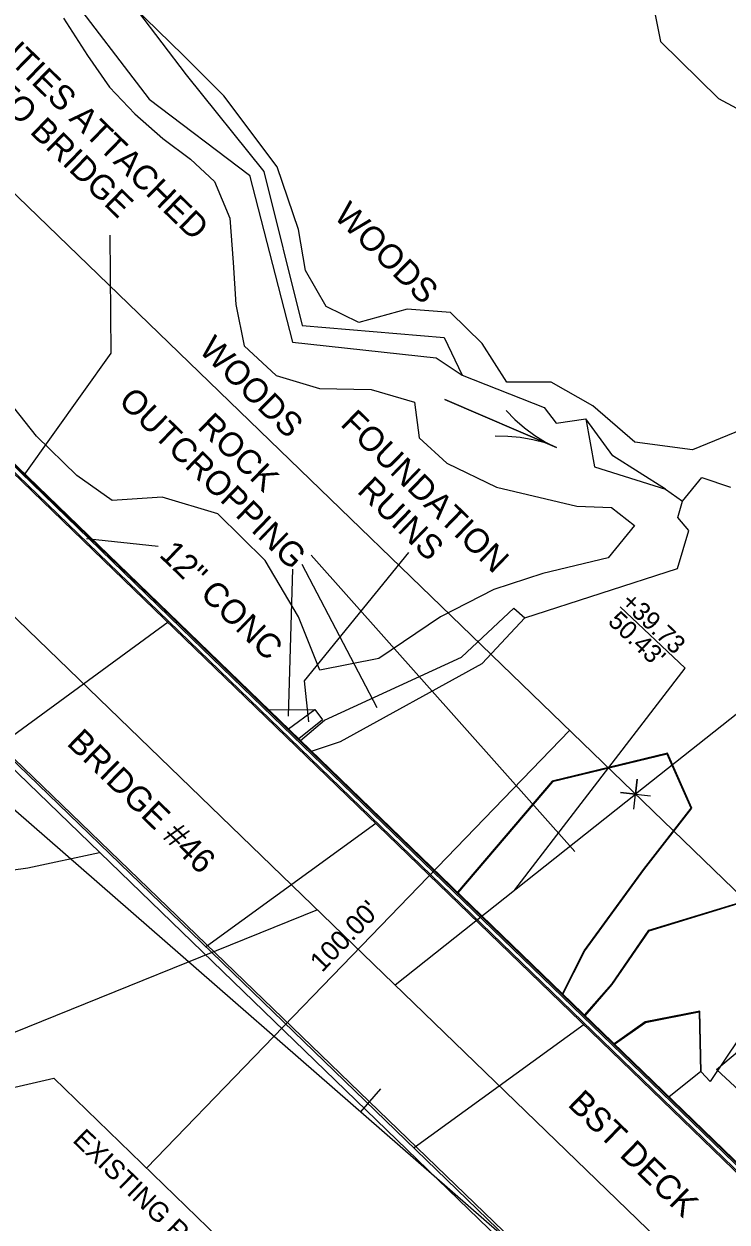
# Model space of a CAD drawing. Extents: x 1977096 to 1980486, y 845025 to 848427.
# Drawn here: x 1978960.3 to 1979075.8, y 846401.8 to 846598.7 of the extents above; entities that cross this region are included whole.
import ezdxf

# ---------------------------------------------------------------- set-up
doc = ezdxf.new("R2010")
doc.units = 0
for name, color, linetype in [('Exist Building Foundations', 7, 'Continuous'), ('Exist Building Foundations Text', 7, 'Continuous'), ('Exist Horizontal Alignment', 7, 'Continuous'), ('Exist Horizontal Baseline Alignment', 7, 'Continuous'), ('Exist Horizontal Baseline Alignment Tick small', 7, 'Continuous'), ('Exist Hydro Jurisdictional Stream or Body of Water', 7, 'Continuous'), ('Exist Hydro River Flow Arrow CELL', 7, 'Continuous'), ('Exist Hydro Stream or Body of Water', 7, 'Continuous'), ('Exist Other Culture Area Outline', 7, 'Continuous'), ('Exist Other Culture Area Outline Text', 7, 'Continuous'), ('Exist Property Corner CELL', 7, 'Continuous'), ('Exist Property Line', 7, 'Continuous'), ('Exist Property Tie Line', 7, 'Continuous'), ('Exist Property Tie Line Leader', 7, 'Continuous'), ('Exist Property Tie Line Text', 7, 'Continuous'), ('Exist Right of Way Line', 7, 'Continuous'), ('Exist Right of Way Line Text', 7, 'Continuous'), ('Exist Right of Way Width CELL', 7, 'Continuous'), ('Exist Roads Curbs', 7, 'Continuous'), ('Exist Roads Curbs Text', 7, 'Continuous'), ('Exist Structure Major Bridge Seam', 7, 'Continuous'), ('Exist Structure Major Deck Tunnel Box Culvert', 7, 'Continuous'), ('Exist Structure Major Deck Tunnel Box Culvert Text', 7, 'Continuous'), ('Exist Utilities Telephone UG Cable SUE LOS B', 7, 'Continuous'), ('Exist Utilities Telephone UG Cable SUE LOS C', 7, 'Continuous'), ('Exist Vegetation Woods Line', 7, 'Continuous'), ('Exist Vegetation Woods Line Text', 7, 'Continuous')]:
    doc.layers.add(name, color=color, linetype=linetype)

msp = doc.modelspace()

# ---------------------------------------------------------------- linework, layer by layer
at = {"layer": 'Exist Building Foundations'}
msp.add_line((1979008.12, 846486.05), (1979009.38, 846484.33), dxfattribs=at)
for points in [[(1979003.79, 846482.85), (1979008.12, 846486.05)], [(1979009.38, 846484.33), (1979005.48, 846481.22)]]:
    msp.add_lwpolyline(points, dxfattribs=at)
at = {"layer": 'Exist Building Foundations Text'}
msp.add_lwpolyline([(1979007.14, 846484), (1979006.43, 846490.74), (1979023.54, 846511.84)], dxfattribs=at)
at = {"layer": 'Exist Horizontal Alignment'}
msp.add_line((1978489.47, 846954.95), (1979491.73, 845985.98), dxfattribs=at)
at = {"layer": 'Exist Horizontal Baseline Alignment'}
msp.add_line((1978896.27, 846524.09), (1979767.77, 845764.02), dxfattribs=at)
at = {"layer": 'Exist Horizontal Baseline Alignment Tick small'}
msp.add_line((1979015.67, 846419.95), (1979018.96, 846423.72), dxfattribs=at)
at = {"layer": 'Exist Hydro Jurisdictional Stream or Body of Water'}
for points in [[(1978853.63, 846668.95), (1978854.24, 846669.93), (1978861.68, 846672.04), (1978865.07, 846675.39), (1978876.61, 846673.36), (1978885.7, 846670.69), (1978907.22, 846666.09), (1978915.17, 846651.15), (1978926.63, 846641.14), (1978944.18, 846642.75), (1978957.12, 846633.12), (1978970.97, 846611.43), (1978986.97, 846590.3), (1978999.76, 846574.43), (1979006.05, 846549.12), (1979029.35, 846547.16), (1979032.35, 846540.96)], [(1978858.23, 846664.13), (1978874.03, 846664.83), (1978876.65, 846665.59), (1978885.24, 846666.34), (1978904.56, 846662.62), (1978911.78, 846649.64), (1978925.49, 846638.04), (1978943.34, 846639.72), (1978953.2, 846627.33), (1978967.14, 846604.37), (1978980.92, 846586.34), (1978997.37, 846573.84), (1979004.46, 846546.41), (1979028.06, 846543.84)], [(1979028.06, 846543.84), (1979032.35, 846540.96)], [(1979032.35, 846540.96), (1979045.81, 846535.65), (1979047.78, 846533.12), (1979052.65, 846533.81), (1979054.06, 846525.92), (1979065.75, 846522.26)], [(1979032.35, 846540.96), (1979032.35, 846540.96)], [(1979068.53, 846520.3), (1979071.68, 846524.18), (1979076.4, 846522.59)], [(1979069.56, 846515.48), (1979067.75, 846517.62), (1979068.53, 846520.3)], [(1979035.63, 846493.6), (1979042.64, 846501.09), (1979067.71, 846509.24), (1979069.56, 846515.48)], [(1979007.57, 846479.2), (1979012.33, 846480.8), (1979035.63, 846493.6)], [(1979062.97, 846449.78), (1979079.75, 846454.91), (1979088.1, 846465.92), (1979099.55, 846462)], [(1978717.4, 846362.79), (1978747.02, 846380.6), (1978772.8, 846397.5), (1978820.46, 846414.82), (1978860.42, 846436.03), (1978899.42, 846449.31), (1978931.62, 846455.92), (1978960.98, 846460.02), (1978972.76, 846462.58)], [(1979052.45, 846435.81), (1979056.9, 846440.93), (1979062.97, 846449.78)]]:
    msp.add_lwpolyline(points, dxfattribs=at)
at = {"layer": 'Exist Hydro River Flow Arrow CELL'}
msp.add_line((1979038.66, 846533.05), (1979038.66, 846533.05), dxfattribs=at)
msp.add_lwpolyline([(1979039.57, 846535.15), (1979040.99, 846533.68), (1979042.55, 846532.31), (1979044.24, 846531.07), (1979046, 846529.98), (1979047.85, 846529.1), (1979029.48, 846537), (1979047.85, 846529.1), (1979045.94, 846529.84), (1979043.93, 846530.36), (1979041.87, 846530.73), (1979039.81, 846530.92), (1979037.76, 846530.95)], dxfattribs=at)
at = {"layer": 'Exist Hydro Stream or Body of Water'}
msp.add_line((1979065.75, 846522.26), (1979068.53, 846520.3), dxfattribs=at)
for points in [[(1979065.75, 846522.26), (1979057.08, 846527.75), (1979052.65, 846533.81)], [(1979048.87, 846439.27), (1979052.48, 846446.38), (1979062.18, 846459.69), (1979070.08, 846469.84), (1979066.06, 846478.86), (1979047.1, 846474.27), (1979031.55, 846456.02)], [(1979057.37, 846431.06), (1979062.43, 846434.65), (1979071.29, 846436.36), (1979071.51, 846426.51)], [(1979071.51, 846426.51), (1979066.33, 846422.39)]]:
    msp.add_lwpolyline(points, dxfattribs=at)
at = {"layer": 'Exist Other Culture Area Outline'}
for points in [[(1979005.74, 846480.97), (1979009.72, 846484.28), (1979032.21, 846494.63), (1979040.83, 846502.69), (1979042.64, 846501.09)], [(1979000.52, 846486.01), (1979008.12, 846486.05)], [(1979048.79, 846439.35), (1979052.39, 846446.43), (1979062.1, 846459.75), (1979069.97, 846469.86), (1979066, 846478.74), (1979047.16, 846474.18), (1979031.62, 846455.95)], [(1979052.52, 846435.74), (1979056.98, 846440.87), (1979063.03, 846449.7), (1979079.81, 846454.83), (1979088.14, 846465.8), (1979099.46, 846461.92), (1979100.45, 846458.89)], [(1979100.45, 846458.89), (1979089.8, 846449.8), (1979073.07, 846424.91), (1979071.61, 846426.51)], [(1979071.61, 846426.51), (1979071.39, 846436.48), (1979062.39, 846434.74), (1979057.29, 846431.13)]]:
    msp.add_lwpolyline(points, dxfattribs=at)
at = {"layer": 'Exist Other Culture Area Outline Text'}
for p, q in [((1979050.83, 846462.72), (1979007.54, 846511.42)), ((1979003.77, 846484.97), (1979004.51, 846509.09)), ((1979018.35, 846486.35), (1979006.03, 846509.88))]:
    msp.add_line(p, q, dxfattribs=at)
msp.add_lwpolyline([(1978960.38, 846524.56), (1978974.68, 846544.62), (1978974.5, 846564)], dxfattribs=at)
at = {"layer": 'Exist Property Corner CELL'}
msp.add_line((1979060.8, 846472.14), (1979060.8, 846472.14), dxfattribs=at)
msp.add_lwpolyline([(1979060.52, 846469.66), (1979061.09, 846474.63), (1979060.8, 846472.14), (1979058.32, 846472.43), (1979063.29, 846471.86)], dxfattribs=at)
at = {"layer": 'Exist Property Line'}
msp.add_line((1979162.74, 846553.05), (1979060.8, 846472.14), dxfattribs=at)
at = {"layer": 'Exist Property Tie Line'}
for p, q in [((1979021.3, 846440.79), (1979060.8, 846472.14)), ((1979008.54, 846453.13), (1978907.03, 846412.17))]:
    msp.add_line(p, q, dxfattribs=at)
at = {"layer": 'Exist Property Tie Line Leader'}
msp.add_lwpolyline([(1979040.97, 846456.41), (1979068.94, 846492.87), (1979058.31, 846502.94)], dxfattribs=at)
at = {"layer": 'Exist Right of Way Line'}
for p, q in [((1978524.22, 846990.9), (1979641.56, 845910.68)), ((1978907.03, 846412.17), (1978965.22, 846425.46)), ((1978965.22, 846425.46), (1979456.98, 845950.04))]:
    msp.add_line(p, q, dxfattribs=at)
at = {"layer": 'Exist Right of Way Width CELL'}
for p in [(1979049.97, 846482.62), (1978980.47, 846410.72)]:
    msp.add_line(p, (1979015.82, 846447.29), dxfattribs=at)
at = {"layer": 'Exist Roads Curbs'}
for p, q in [((1978950.41, 846534.47), (1979122.22, 846368.35)), ((1978949.71, 846533.75), (1979121.53, 846367.63)), ((1978920.3, 846513.29), (1979092.15, 846347.16)), ((1978921, 846514.01), (1979092.85, 846347.88))]:
    msp.add_line(p, q, dxfattribs=at)
at = {"layer": 'Exist Roads Curbs Text'}
msp.add_line((1978970.6, 846514.16), (1978982.36, 846512.91), dxfattribs=at)
at = {"layer": 'Exist Structure Major Bridge Seam'}
for p, q in [((1978956.15, 846480.09), (1978984, 846500.47)), ((1979018.16, 846467.32), (1978990.32, 846447.1)), ((1979024.46, 846414.09), (1979052.37, 846434.35))]:
    msp.add_line(p, q, dxfattribs=at)
at = {"layer": 'Exist Structure Major Deck Tunnel Box Culvert'}
msp.add_lwpolyline([(1978949.98, 846533.2), (1979120.24, 846368.57), (1979092.73, 846348.59), (1978922.38, 846513.01), (1978949.98, 846533.2)], dxfattribs=at)
at = {"layer": 'Exist Utilities Telephone UG Cable SUE LOS B'}
msp.add_lwpolyline([(1978827.65, 846546.54), (1978851.92, 846542.32), (1978879.52, 846535.99), (1978884.35, 846535.6), (1978891.83, 846534.67), (1978899.37, 846538.39), (1978920.22, 846556.85), (1978924.91, 846559.45), (1978950.09, 846536.12), (1978950.33, 846534.15), (1978987.97, 846497.66), (1979030.84, 846456.21), (1979068.41, 846419.87), (1979104.74, 846384.73), (1979121.49, 846368.64), (1979124.13, 846367.89), (1979158.73, 846334.37), (1979169.87, 846328.36), (1979184.39, 846326.33), (1979188.6, 846324.61), (1979192.59, 846322.26), (1979193.41, 846321.34)], dxfattribs=at)
at = {"layer": 'Exist Utilities Telephone UG Cable SUE LOS C'}
msp.add_lwpolyline([(1978816.58, 846668.11), (1978851.59, 846633.51), (1978891.39, 846594.5), (1978926.18, 846560.72), (1978950.49, 846536.73), (1978950.45, 846534.27), (1978988.14, 846497.85), (1979031.03, 846456.38), (1979068.6, 846420.04), (1979104.92, 846384.91), (1979120.52, 846369.7), (1979122.4, 846366.47), (1979156.61, 846333.43), (1979168.3, 846321.97), (1979173, 846324.46), (1979186.35, 846322.12), (1979192.31, 846321.61), (1979193.41, 846321.34)], dxfattribs=at)
at = {"layer": 'Exist Vegetation Woods Line'}
for points in [[(1979009.03, 846642.22), (1979014.82, 846636.84), (1979022.83, 846627.18), (1979028.61, 846615.25), (1979034.58, 846605.13), (1979041.75, 846603.1), (1979046.93, 846606.8), (1979051.12, 846616.69), (1979058.33, 846619.16), (1979061.91, 846610.94), (1979064.9, 846595.81), (1979074.45, 846586.44), (1979083.32, 846581.66), (1979096.37, 846584.12), (1979108.07, 846596.34), (1979118.5, 846610.12), (1979129.21, 846613.78), (1979138, 846619.97), (1979142.95, 846632.94), (1979151.87, 846643.03), (1979160.2, 846645.56), (1979160.56, 846645.79)], [(1979078.33, 846532.03), (1979070.17, 846528.7), (1979060.71, 846529.96), (1979053.8, 846535.93), (1979046.93, 846539.85), (1979039.65, 846539.81), (1979035.64, 846546.21), (1979030.43, 846551.25), (1979023.31, 846551.81), (1979015.33, 846549.64), (1979009.97, 846552.27), (1979006.61, 846558.17), (1979005.43, 846564.9), (1979001.91, 846575.22), (1978993.19, 846586.85), (1978986.51, 846593.55), (1978978.15, 846601.65)], [(1978966.84, 846599.64), (1978970.78, 846593.49), (1978974.37, 846588.3), (1978978.52, 846583.91), (1978983.16, 846579.85), (1978987.68, 846576.47), (1978991.62, 846572.81), (1978994.14, 846566.8), (1978994.72, 846559.48), (1978995.16, 846552.58), (1978996.53, 846545.81), (1979001.77, 846540.91), (1979008.9, 846538.78), (1979017.37, 846538.64), (1979024.5, 846536.56), (1979025.27, 846530.66), (1979029.8, 846526.55), (1979037.99, 846522.57), (1979051.17, 846519.44), (1979056.89, 846519.25), (1979060.62, 846516.27), (1979056.34, 846510.95), (1979045.56, 846508.37), (1979037.52, 846505.77), (1979028.76, 846501.25), (1979018.65, 846494.41), (1979008.92, 846492.53), (1979005.43, 846501.25), (1978999.95, 846510.51), (1978992.16, 846518.19), (1978983.03, 846520.93), (1978974.8, 846520.4), (1978969.01, 846524.49), (1978962.39, 846530.97), (1978956.82, 846538)], [(1979086.85, 846415.09), (1979074.09, 846426.92), (1979086.15, 846437.04)]]:
    msp.add_lwpolyline(points, dxfattribs=at)

# ---------------------------------------------------------------- texts
at = {"layer": 'Exist Building Foundations Text'}
for s, p in [('FOUNDATION', (1979012.17, 846532.79)), ('RUINS', (1979014.91, 846521.8))]:
    msp.add_text(s, height=4, rotation=315.9733, dxfattribs=at).set_placement(p)
at = {"layer": 'Exist Other Culture Area Outline Text'}
for s, rotation, p in [('UTILITIES ATTACHED', 315.8604, (1978948.59, 846601.39)), ('TO BRIDGE', 315.8604, (1978954.75, 846587.05)), ('OUTCROPPING', 315.9733, (1978975.69, 846536.49)), ('ROCK', 315.9733, (1978988.67, 846532.29))]:
    msp.add_text(s, height=4, rotation=rotation, dxfattribs=at).set_placement(p)
at = {"layer": 'Exist Property Tie Line Text'}
for s, p in [('+39.73', (1979058.25, 846503.46)), ("50.43'", (1979056.12, 846500.31))]:
    msp.add_text(s, height=3, rotation=316.6382, dxfattribs=at).set_placement(p)
at = {"layer": 'Exist Right of Way Line Text'}
msp.add_text('EXISTING R/W', height=3.2, rotation=315.9677, dxfattribs=at).set_placement((1978968.17, 846415.14))
at = {"layer": 'Exist Right of Way Width CELL'}
msp.add_text("100.00'", height=3.2, rotation=45.9677, dxfattribs=at).set_placement((1979009.3, 846442.74))
at = {"layer": 'Exist Roads Curbs Text'}
msp.add_text('12" CONC', height=4, rotation=315.966, dxfattribs=at).set_placement((1978982.39, 846511.31))
at = {"layer": 'Exist Structure Major Deck Tunnel Box Culvert Text'}
for s, p in [('BRIDGE #46', (1978967.2, 846480.35)), ('BST DECK', (1979049.5, 846421.03))]:
    msp.add_text(s, height=4, rotation=315.8158, dxfattribs=at).set_placement(p)
at = {"layer": 'Exist Vegetation Woods Line Text'}
for p in [(1979011.08, 846566.95), (1978988.89, 846544.94)]:
    msp.add_text('WOODS', height=4, rotation=315.6543, dxfattribs=at).set_placement(p)

doc.saveas('drawing.dxf')
